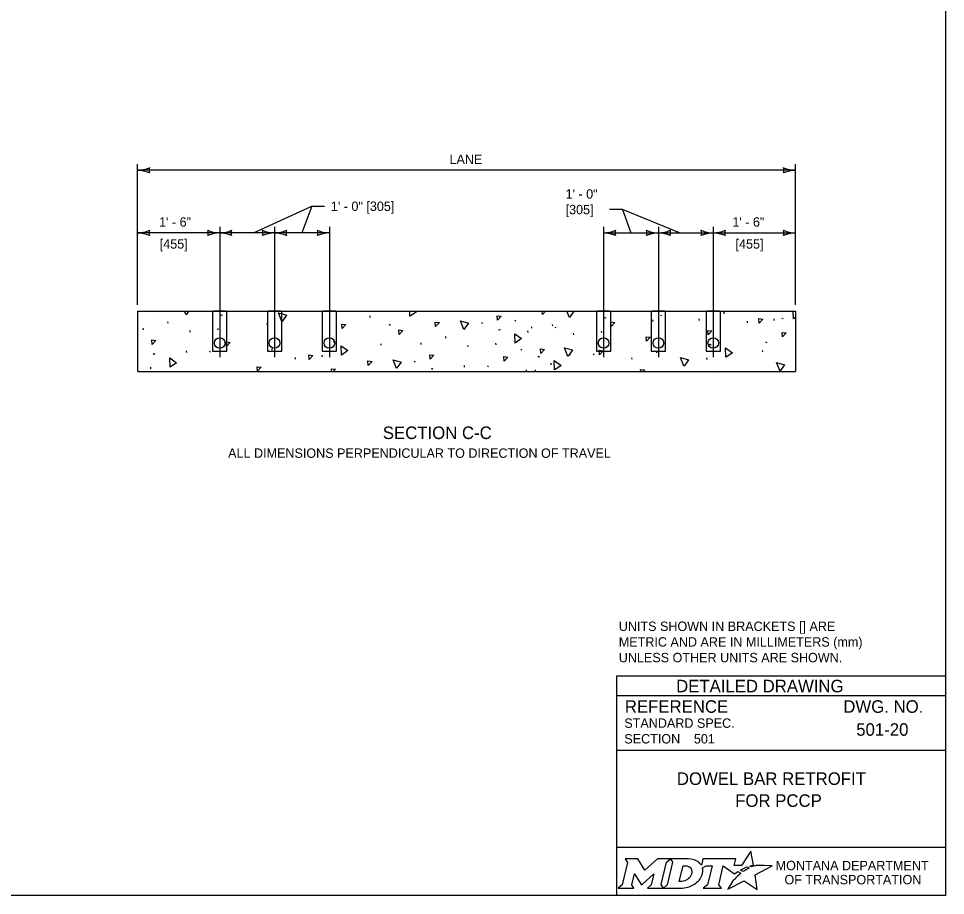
# Model space of a CAD drawing. Extents: x 49991.4 to 50021, y 49987.6 to 50011.4.
# Drawn here: x 50010.83 to 50016.75, y 49987.8 to 49993.4 of the extents above; entities that cross this region are included whole.
import ezdxf

# ---------------------------------------------------------------- set-up
doc = ezdxf.new("R2010")
doc.units = 0
for name, color, linetype in [('Default', 7, 'Continuous'), ('Level 1', 7, 'Continuous'), ('Level 2', 7, 'Continuous'), ('Level 3', 7, 'Continuous'), ('Level 4', 7, 'Continuous'), ('Level 5', 7, 'Continuous'), ('Level 9', 7, 'Continuous')]:
    doc.layers.add(name, color=color, linetype=linetype)

msp = doc.modelspace()

# ---------------------------------------------------------------- linework, layer by layer
at = {"layer": 'Default'}
for points in [[(50014.7056, 49988.0338), (50014.7197, 49988.0104), (50014.6862, 49987.8671), (50014.6605, 49987.8446), (50014.7621, 49987.8446), (50014.7486, 49987.8674), (50014.7648, 49987.9375), (50014.8085, 49987.8685), (50014.8138, 49987.8685), (50014.8889, 49987.938), (50014.8725, 49987.8669), (50014.8478, 49987.8449), (50014.9494, 49987.8449), (50014.9356, 49987.8682), (50014.9688, 49988.0106)], [(50014.9688, 49988.0106), (50014.9941, 49988.0338), (50014.9117, 49988.0338), (50014.8321, 49987.9608), (50014.7876, 49988.0335), (50014.7056, 49988.0338)], [(50015.1077, 49988.0338), (50014.9941, 49988.0338), (50015.0088, 49988.0109), (50014.9749, 49987.8671), (50014.9494, 49987.8449), (50015.06, 49987.8449)], [(50015.5126, 49987.9811), (50015.5023, 49987.9867), (50015.5139, 49987.9895), (50015.5255, 49987.9915), (50015.5081, 49988.0816), (50015.4486, 49987.9903), (50015.4013, 49987.9896), (50015.4116, 49988.0337), (50015.2024, 49988.0338), (50015.1923, 49987.9913), (50015.1865, 49987.9996)], [(50015.1317, 49987.9471), (50015.1305, 49987.939), (50015.1273, 49987.9297), (50015.1231, 49987.9215), (50015.1175, 49987.914), (50015.111, 49987.9071), (50015.1031, 49987.9008), (50015.0948, 49987.8961), (50015.0857, 49987.8922), (50015.0766, 49987.8899), (50015.0674, 49987.889), (50015.0515, 49987.889), (50015.0751, 49987.989), (50015.0911, 49987.989), (50015.0987, 49987.9884), (50015.1063, 49987.9865), (50015.1129, 49987.9835), (50015.119, 49987.9793), (50015.1238, 49987.9743), (50015.1275, 49987.9683), (50015.1302, 49987.9621), (50015.1318, 49987.9547), (50015.1318, 49987.9517), (50015.1317, 49987.9471)], [(50015.1991, 49987.9747), (50015.2237, 49987.9878), (50015.2606, 49987.9878), (50015.232, 49987.8673), (50015.2045, 49987.8446), (50015.3207, 49987.8446), (50015.3037, 49987.8675), (50015.3319, 49987.9877), (50015.4032, 49987.936), (50015.4243, 49987.9511), (50015.444, 49987.9402)], [(50015.3882, 49987.8843), (50015.3729, 49987.8599), (50015.3682, 49987.8524), (50015.3624, 49987.8438), (50015.3601, 49987.8395), (50015.4654, 49987.8926), (50015.5493, 49987.8375), (50015.5362, 49987.9302), (50015.6431, 49987.9886), (50015.5938, 49987.9894), (50015.5637, 49987.9898), (50015.5429, 49987.9901), (50015.5361, 49987.9886), (50015.5312, 49987.9874), (50015.5228, 49987.9851), (50015.5126, 49987.9811)], [(50015.4622, 49987.9535), (50015.4598, 49987.9518), (50015.4415, 49987.9614), (50015.4518, 49987.9671), (50015.4559, 49987.9693), (50015.4645, 49987.9733), (50015.4702, 49987.9759), (50015.4781, 49987.9789), (50015.4854, 49987.9816), (50015.4972, 49987.9742), (50015.4932, 49987.9721), (50015.4886, 49987.9696), (50015.4844, 49987.9674), (50015.4794, 49987.9645), (50015.4775, 49987.9634), (50015.4748, 49987.9618), (50015.4723, 49987.9604), (50015.47, 49987.9588), (50015.4674, 49987.957), (50015.4647, 49987.9552), (50015.4622, 49987.9535)], [(50015.1057, 49987.8522), (50015.1141, 49987.8548), (50015.1271, 49987.8602), (50015.1475, 49987.8712)], [(50015.4021, 49987.9004), (50015.4021, 49987.9004)]]:
    msp.add_lwpolyline(points, dxfattribs=at)
for centre, radius, start, end in [((50015.1308, 49987.9554), 0.0709, 339.53292, 15.85821), ((50015.0868, 49987.9727), 0.1183, 300.91025, 339.13831)]:
    msp.add_arc(centre, radius, start, end, dxfattribs=at)
for centre, major_axis, ratio, start_param, end_param in [((50015.1056, 49987.9864), (0.0834, -0.0037), 0.568097, 0.61298, 1.570796), ((50015.1612, 49987.9937), (0.0361, -0.0295), 0.469099, 1.225588, 1.570796), ((50015.4119, 49987.9106), (-0.0098, -0.0102), 0.016458, 3.141593, 6.279097), ((50015.4329, 49987.9305), (-0.0112, -0.0097), 0.021651, 3.157348, 6.283185), ((50015.3952, 49987.8923), (-0.00694, -0.00806), 0.008222, 0, 3.137361), ((50015.0603, 49987.9932), (0, 0.1484), 0.987302, 3.139398, 3.456847)]:
    msp.add_ellipse(centre, major_axis=major_axis, ratio=ratio, start_param=start_param, end_param=end_param, dxfattribs=at)
at = {"layer": 'Level 1'}
for p, q in [((50011.5929, 49991.5298), (50011.5929, 49991.1448)), ((50011.5929, 49991.5298), (50015.7929, 49991.5298)), ((50015.7929, 49991.5298), (50015.7929, 49991.1448)), ((50011.5952, 49991.1448), (50015.7929, 49991.1448))]:
    msp.add_line(p, q, dxfattribs=at)
msp.add_lwpolyline([(49999.3835, 49998.9992), (50016.7501, 49998.9992), (50016.7501, 49987.7988), (49999.3835, 49987.7988)], close=True, dxfattribs=at)
at = {"layer": 'Level 3'}
for p, q in [((50011.5929, 49991.5698), (50011.5929, 49992.4698)), ((50015.7929, 49992.4298), (50011.5929, 49992.4298)), ((50015.7929, 49991.5698), (50015.7929, 49992.4698)), ((50012.7055, 49992.2002), (50012.7874, 49992.2002)), ((50014.6882, 49992.179), (50014.6062, 49992.179)), ((50012.1179, 49992.0298), (50011.5929, 49992.0298)), ((50012.4679, 49992.0298), (50012.1179, 49992.0298)), ((50012.8179, 49992.0298), (50012.4679, 49992.0298)), ((50014.5679, 49992.0298), (50014.9179, 49992.0298)), ((50014.9179, 49992.0298), (50015.2679, 49992.0298)), ((50015.2679, 49992.0298), (50015.7929, 49992.0298))]:
    msp.add_line(p, q, dxfattribs=at)
for points in [[(50012.3342, 49992.0298), (50012.7055, 49992.2002), (50012.6429, 49992.0298)], [(50015.0517, 49992.0298), (50014.6882, 49992.179), (50014.7429, 49992.0298)]]:
    msp.add_lwpolyline(points, dxfattribs=at)
for centre in [(50012.1179, 49991.3267), (50012.4679, 49991.3267), (50012.8179, 49991.3267), (50014.5679, 49991.3267), (50014.9179, 49991.3267), (50015.2679, 49991.3267)]:
    msp.add_circle(centre, 0.0338, dxfattribs=at)
for centre, radius, start, end in [((50011.5838, 49992.6519), 0.2223, 272.36048, 292.54399), ((50011.5815, 49992.1971), 0.233, 67.92284, 87.17269), ((50011.7212, 49992.4298), 0.0548, 162.13882, 197.86118), ((50015.8021, 49992.6519), 0.2223, 247.45601, 267.63952), ((50015.6647, 49992.4298), 0.0548, 342.13882, 17.86118), ((50015.8044, 49992.1971), 0.233, 92.82731, 112.07716), ((50011.5838, 49992.2519), 0.2223, 272.36048, 292.54399), ((50011.5815, 49991.7971), 0.233, 67.92284, 87.17269), ((50011.7212, 49992.0298), 0.0548, 162.13882, 197.86118), ((50011.9897, 49992.0298), 0.0548, 342.13882, 17.86118), ((50012.1294, 49992.2625), 0.233, 247.92284, 267.17269), ((50012.1271, 49991.8076), 0.2223, 92.36048, 112.54399), ((50012.1088, 49992.2519), 0.2223, 272.36048, 292.54399), ((50012.1065, 49991.7971), 0.233, 67.92284, 87.17269), ((50012.2462, 49992.0298), 0.0548, 162.13882, 197.86118), ((50012.3397, 49992.0298), 0.0548, 342.13882, 17.86118), ((50012.4794, 49992.2625), 0.233, 247.92284, 267.17269), ((50012.4771, 49991.8076), 0.2223, 92.36048, 112.54399), ((50012.4588, 49992.2519), 0.2223, 272.36048, 292.54399), ((50012.4565, 49991.7971), 0.233, 67.92284, 87.17269), ((50012.5962, 49992.0298), 0.0548, 162.13882, 197.86118), ((50012.6897, 49992.0298), 0.0548, 342.13882, 17.86118), ((50012.8294, 49992.2625), 0.233, 247.92284, 267.17269), ((50012.8271, 49991.8076), 0.2223, 92.36048, 112.54399), ((50014.5564, 49992.2625), 0.233, 272.82731, 292.07716), ((50014.5588, 49991.8076), 0.2223, 67.45601, 87.63952), ((50014.6961, 49992.0298), 0.0548, 162.13882, 197.86118), ((50014.9271, 49992.2519), 0.2223, 247.45601, 267.63952), ((50014.7897, 49992.0298), 0.0548, 342.13882, 17.86118), ((50014.9294, 49991.7971), 0.233, 92.82731, 112.07716), ((50014.9064, 49992.2625), 0.233, 272.82731, 292.07716), ((50014.9088, 49991.8076), 0.2223, 67.45601, 87.63952), ((50015.0461, 49992.0298), 0.0548, 162.13882, 197.86118), ((50015.2771, 49992.2519), 0.2223, 247.45601, 267.63952), ((50015.1397, 49992.0298), 0.0548, 342.13882, 17.86118), ((50015.2794, 49991.7971), 0.233, 92.82731, 112.07716), ((50015.2564, 49992.2625), 0.233, 272.82731, 292.07716), ((50015.2588, 49991.8076), 0.2223, 67.45601, 87.63952), ((50015.3961, 49992.0298), 0.0548, 162.13882, 197.86118), ((50015.8021, 49992.2519), 0.2223, 247.45601, 267.63952), ((50015.6647, 49992.0298), 0.0548, 342.13882, 17.86118), ((50015.8044, 49991.7971), 0.233, 92.82731, 112.07716)]:
    msp.add_arc(centre, radius, start, end, dxfattribs=at)
at = {"layer": 'Level 4'}
for p, q in [((50014.4676, 49991.5298), (50014.4681, 49991.5291)), ((50012.1233, 49991.5071), (50012.1299, 49991.5038)), ((50012.128, 49991.5071), (50012.1347, 49991.5038)), ((50013.0792, 49991.4904), (50013.0782, 49991.5006)), ((50014.0007, 49991.4727), (50014.0074, 49991.4694)), ((50014.5708, 49991.4904), (50014.5775, 49991.4871)), ((50014.5756, 49991.4905), (50014.5823, 49991.4871)), ((50014.8842, 49991.4643), (50014.8831, 49991.4745)), ((50014.9307, 49991.5054), (50014.9374, 49991.5021)), ((50015.1801, 49991.4712), (50015.1791, 49991.4813)), ((50015.3377, 49991.5131), (50015.3367, 49991.5233)), ((50015.4872, 49991.4562), (50015.4861, 49991.4664)), ((50015.6578, 49991.4705), (50015.6568, 49991.4807)), ((50015.7066, 49991.4863), (50015.7133, 49991.483)), ((50011.631, 49991.4107), (50011.6299, 49991.4208)), ((50011.7886, 49991.4527), (50011.7875, 49991.4628)), ((50011.9303, 49991.3957), (50011.9293, 49991.4059)), ((50012.1087, 49991.41), (50012.1076, 49991.4202)), ((50012.4227, 49991.4405), (50012.4216, 49991.4506)), ((50013.1996, 49991.4469), (50013.2051, 49991.4393)), ((50013.7882, 49991.4595), (50013.7938, 49991.4519)), ((50013.8966, 49991.4133), (50013.9032, 49991.41)), ((50013.9013, 49991.4133), (50013.908, 49991.41)), ((50014.1111, 49991.4209), (50014.11, 49991.4311)), ((50014.2434, 49991.436), (50014.2424, 49991.4461)), ((50014.2564, 49991.4283), (50014.2631, 49991.4249)), ((50013.5619, 49991.3588), (50013.5608, 49991.369)), ((50014.0858, 49991.394), (50014.0848, 49991.4042)), ((50014.3779, 49991.3791), (50014.3769, 49991.3892)), ((50014.5563, 49991.3933), (50014.5552, 49991.4035)), ((50012.4532, 49991.2817), (50012.4521, 49991.2918)), ((50012.8429, 49991.3361), (50012.8496, 49991.3328)), ((50013.1493, 49991.3122), (50013.1482, 49991.3223)), ((50013.4043, 49991.3169), (50013.4032, 49991.327)), ((50013.7036, 49991.3019), (50013.7026, 49991.312)), ((50013.882, 49991.3162), (50013.8809, 49991.3263)), ((50014.04, 49991.2885), (50014.0456, 49991.2809)), ((50015.2426, 49991.3194), (50015.2493, 49991.3161)), ((50015.2474, 49991.3195), (50015.2541, 49991.3162)), ((50015.6024, 49991.3344), (50015.6091, 49991.3311)), ((50011.6935, 49991.259), (50011.7002, 49991.2556)), ((50011.6982, 49991.259), (50011.7049, 49991.2557)), ((50011.908, 49991.2666), (50011.9069, 49991.2768)), ((50012.0533, 49991.2739), (50012.06, 49991.2706)), ((50012.6021, 49991.2247), (50012.601, 49991.2349)), ((50012.7733, 49991.239), (50012.7722, 49991.2492)), ((50014.1483, 49991.2423), (50014.155, 49991.239)), ((50014.1531, 49991.2423), (50014.1598, 49991.239)), ((50014.3556, 49991.2499), (50014.3545, 49991.2601)), ((50014.5009, 49991.2573), (50014.5076, 49991.254)), ((50014.7503, 49991.2231), (50014.7493, 49991.2332)), ((50014.908, 49991.265), (50014.9069, 49991.2752)), ((50015.2281, 49991.2224), (50015.227, 49991.2325)), ((50015.5841, 49991.2699), (50015.5831, 49991.28)), ((50011.6789, 49991.1619), (50011.6779, 49991.172)), ((50013.3585, 49991.2113), (50013.364, 49991.2038)), ((50013.6813, 49991.1728), (50013.6802, 49991.1829)), ((50013.8266, 49991.1801), (50013.8333, 49991.1768)), ((50014.2337, 49991.1879), (50014.2326, 49991.198)), ((50013.4668, 49991.1651), (50013.4735, 49991.1618)), ((50013.4715, 49991.1652), (50013.4782, 49991.1618)), ((50014.0761, 49991.1459), (50014.075, 49991.156)), ((50014.1338, 49991.1452), (50014.1327, 49991.1554))]:
    msp.add_line(p, q, dxfattribs=at)
for points in [[(50011.7229, 49991.5254), (50011.7226, 49991.5298)], [(50011.7269, 49991.5298), (50011.7229, 49991.5254)], [(50011.9031, 49991.5064), (50011.8936, 49991.5298)], [(50011.9197, 49991.5298), (50011.9038, 49991.5072)], [(50013.3322, 49991.4978), (50013.331, 49991.5298)], [(50013.3682, 49991.5298), (50013.3732, 49991.5262), (50013.3331, 49991.4983)], [(50014.1778, 49991.5087), (50014.1762, 49991.5298)], [(50014.1971, 49991.5298), (50014.1778, 49991.5087)], [(50014.3507, 49991.4897), (50014.3344, 49991.5298)], [(50014.379, 49991.5298), (50014.3514, 49991.4905)], [(50015.7798, 49991.4811), (50015.778, 49991.5298)], [(50012.5151, 49991.4645), (50012.4926, 49991.5198), (50012.5439, 49991.5052), (50012.5158, 49991.4652)], [(50013.6764, 49991.4126), (50013.6539, 49991.468), (50013.7052, 49991.4533), (50013.6771, 49991.4134)], [(50013.8903, 49991.4718), (50013.8881, 49991.5005), (50013.9138, 49991.4974), (50013.8903, 49991.4718)], [(50015.5602, 49991.4543), (50015.5581, 49991.483), (50015.5838, 49991.4799), (50015.5602, 49991.4543)], [(50015.7929, 49991.4901), (50015.7807, 49991.4816)], [(50012.9004, 49991.419), (50012.8982, 49991.4477), (50012.9239, 49991.4446), (50012.9004, 49991.419)], [(50013.2625, 49991.3822), (50013.2603, 49991.4108), (50013.286, 49991.4077), (50013.2625, 49991.3822)], [(50013.4962, 49991.4316), (50013.494, 49991.4602), (50013.5197, 49991.4571), (50013.4962, 49991.4316)], [(50014.6169, 49991.4327), (50014.6147, 49991.4614), (50014.6404, 49991.4583), (50014.6169, 49991.4327)], [(50015.2363, 49991.378), (50015.2341, 49991.4067), (50015.2598, 49991.4036), (50015.2363, 49991.378)], [(50014.0039, 49991.3268), (50014.0017, 49991.3865), (50014.0449, 49991.3552), (50014.0048, 49991.3273)], [(50014.8423, 49991.3378), (50014.8401, 49991.3664), (50014.8658, 49991.3633), (50014.8423, 49991.3378)], [(50015.7101, 49991.3655), (50015.7079, 49991.3941), (50015.7336, 49991.391), (50015.7101, 49991.3655)], [(50011.6872, 49991.3175), (50011.685, 49991.3462), (50011.7107, 49991.3431), (50011.6872, 49991.3175)], [(50012.161, 49991.305), (50012.1588, 49991.3337), (50012.1845, 49991.3306), (50012.161, 49991.305)], [(50012.8952, 49991.2496), (50012.893, 49991.3094), (50012.9362, 49991.2781), (50012.8961, 49991.2501)], [(50014.168, 49991.2606), (50014.1658, 49991.2892), (50014.1915, 49991.2861), (50014.168, 49991.2606)], [(50014.3409, 49991.2416), (50014.3184, 49991.297), (50014.3697, 49991.2823), (50014.3416, 49991.2424)], [(50015.3489, 49991.2354), (50015.3467, 49991.2951), (50015.3899, 49991.2638), (50015.3498, 49991.2359)], [(50011.8008, 49991.1725), (50011.7986, 49991.2322), (50011.8418, 49991.2009), (50011.8017, 49991.173)], [(50012.6883, 49991.2225), (50012.6861, 49991.2512), (50012.7118, 49991.2481), (50012.6883, 49991.2225)], [(50013.4605, 49991.2237), (50013.4583, 49991.2524), (50013.484, 49991.2493), (50013.4605, 49991.2237)], [(50013.9343, 49991.2112), (50013.9321, 49991.2398), (50013.9578, 49991.2367), (50013.9343, 49991.2112)], [(50014.5411, 49991.2516), (50014.5389, 49991.2802), (50014.5646, 49991.2771), (50014.5411, 49991.2516)], [(50015.0806, 49991.1788), (50015.0581, 49991.2342), (50015.1094, 49991.2196), (50015.0813, 49991.1796)], [(50012.3589, 49991.1466), (50012.3568, 49991.1752), (50012.3825, 49991.1721), (50012.3589, 49991.1466)], [(50013.0664, 49991.1834), (50013.0642, 49991.2121), (50013.09, 49991.209), (50013.0664, 49991.1834)], [(50013.2466, 49991.1644), (50013.2241, 49991.2198), (50013.2754, 49991.2052), (50013.2473, 49991.1652)], [(50014.2557, 49991.1558), (50014.2535, 49991.2155), (50014.2967, 49991.1842), (50014.2566, 49991.1563)], [(50015.6942, 49991.1478), (50015.6717, 49991.2032), (50015.723, 49991.1885), (50015.6949, 49991.1486)], [(50012.8319, 49991.1448), (50012.8305, 49991.1627), (50012.8563, 49991.1596), (50012.8426, 49991.1448)], [(50014.8054, 49991.1448), (50014.8043, 49991.1585), (50014.8301, 49991.1554), (50014.8202, 49991.1448)], [(50015.2782, 49991.1448), (50015.2781, 49991.146), (50015.2884, 49991.1448)]]:
    msp.add_lwpolyline(points, dxfattribs=at)
at = {"layer": 'Level 5'}
for p, q in [((50012.1179, 49992.0698), (50012.1179, 49991.2367)), ((50012.4679, 49992.0698), (50012.4679, 49991.2367)), ((50012.8179, 49992.0698), (50012.8179, 49991.2367)), ((50014.5679, 49992.0698), (50014.5679, 49991.2367)), ((50014.9179, 49992.0698), (50014.9179, 49991.2367)), ((50015.2679, 49992.0698), (50015.2679, 49991.2367)), ((50016.7501, 49989.1988), (50014.6501, 49989.1988)), ((50014.6501, 49989.1988), (50014.6501, 49987.7988)), ((50016.7501, 49989.0738), (50014.6501, 49989.0738)), ((50016.7501, 49988.7238), (50014.6501, 49988.7238)), ((50016.7501, 49988.1057), (50014.6501, 49988.1057))]:
    msp.add_line(p, q, dxfattribs=at)
at = {"layer": 'Level 9'}
for p, q in [((50012.1582, 49991.5298), (50012.0777, 49991.5298)), ((50012.5082, 49991.5298), (50012.4277, 49991.5298)), ((50012.8582, 49991.5298), (50012.7777, 49991.5298)), ((50014.6082, 49991.5298), (50014.5276, 49991.5298)), ((50014.9582, 49991.5298), (50014.8776, 49991.5298)), ((50015.3082, 49991.5298), (50015.2276, 49991.5298)), ((50012.0719, 49991.5239), (50012.0719, 49991.3561)), ((50012.164, 49991.3561), (50012.164, 49991.5239)), ((50012.4219, 49991.5239), (50012.4219, 49991.3561)), ((50012.514, 49991.3561), (50012.514, 49991.5239)), ((50012.7719, 49991.5239), (50012.7719, 49991.3561)), ((50012.8641, 49991.3561), (50012.8641, 49991.5239)), ((50014.5218, 49991.5239), (50014.5218, 49991.3561)), ((50014.614, 49991.3561), (50014.614, 49991.5239)), ((50014.8718, 49991.5239), (50014.8718, 49991.3561)), ((50014.964, 49991.3561), (50014.964, 49991.5239)), ((50015.2218, 49991.5239), (50015.2218, 49991.3561)), ((50015.314, 49991.3561), (50015.314, 49991.5239)), ((50012.0719, 49991.3561), (50012.0719, 49991.2757)), ((50012.164, 49991.2757), (50012.164, 49991.3561)), ((50012.4219, 49991.3561), (50012.4219, 49991.2757)), ((50012.514, 49991.2757), (50012.514, 49991.3561)), ((50012.7719, 49991.3561), (50012.7719, 49991.2757)), ((50012.8641, 49991.2757), (50012.8641, 49991.3561)), ((50014.5218, 49991.3561), (50014.5218, 49991.2757)), ((50014.614, 49991.2757), (50014.614, 49991.3561)), ((50014.8718, 49991.3561), (50014.8718, 49991.2757)), ((50014.964, 49991.2757), (50014.964, 49991.3561)), ((50015.2218, 49991.3561), (50015.2218, 49991.2757)), ((50015.314, 49991.2757), (50015.314, 49991.3561)), ((50012.0719, 49991.2757), (50012.164, 49991.2757)), ((50012.4219, 49991.2757), (50012.514, 49991.2757)), ((50012.7719, 49991.2757), (50012.8641, 49991.2757)), ((50014.5218, 49991.2757), (50014.614, 49991.2757)), ((50014.8718, 49991.2757), (50014.964, 49991.2757)), ((50015.2218, 49991.2757), (50015.314, 49991.2757))]:
    msp.add_line(p, q, dxfattribs=at)
for centre, start, end in [((50012.0777, 49991.5239), 90, 180), ((50012.1582, 49991.5239), 0, 90), ((50012.4277, 49991.5239), 90, 180), ((50012.5082, 49991.5239), 0, 90), ((50012.7777, 49991.5239), 90, 180), ((50012.8582, 49991.5239), 0, 90), ((50014.5276, 49991.5239), 90, 180), ((50014.6082, 49991.5239), 0, 90), ((50014.8776, 49991.5239), 90, 180), ((50014.9582, 49991.5239), 0, 90), ((50015.2276, 49991.5239), 90, 180), ((50015.3082, 49991.5239), 0, 90)]:
    msp.add_arc(centre, 0.00583, start, end, dxfattribs=at)

# ---------------------------------------------------------------- texts
at = {"layer": 'Default'}
for s, p in [('MONTANA DEPARTMENT', (50015.6663, 49987.96)), ('OF TRANSPORTATION', (50015.7225, 49987.87))]:
    msp.add_text(s, height=0.06, rotation=360, dxfattribs=at).set_placement(p)
at = {"layer": 'Level 2'}
for s, height, p in [('LANE', 0.06, (50013.5845, 49992.4698)), ('1\' - 0"', 0.06, (50014.3257, 49992.249)), ('1\' - 0" [305]', 0.06, (50012.8274, 49992.1702)), ('[305]', 0.06, (50014.3257, 49992.149)), ('1\' - 6"', 0.06, (50011.7307, 49992.0698)), ('1\' - 6"', 0.06, (50015.3899, 49992.0698)), ('[455]', 0.06, (50011.7352, 49991.9298)), ('[455]', 0.06, (50015.4102, 49991.9298)), ('SECTION C-C', 0.08, (50013.159, 49990.7136)), ('ALL DIMENSIONS PERPENDICULAR TO DIRECTION OF TRAVEL', 0.06, (50012.1715, 49990.5936)), ('UNITS SHOWN IN BRACKETS [] ARE ', 0.06, (50014.6651, 49989.488)), ('METRIC AND ARE IN MILLIMETERS (mm) ', 0.06, (50014.6651, 49989.388)), ('UNLESS OTHER UNITS ARE SHOWN.', 0.06, (50014.6651, 49989.288)), ('501-20', 0.08, (50016.1805, 49988.8187)), ('501', 0.06, (50015.1444, 49988.7693)), ('DOWEL BAR RETROFIT', 0.08, (50015.0359, 49988.5047)), ('FOR PCCP', 0.08, (50015.408, 49988.3647))]:
    msp.add_text(s, height=height, dxfattribs=at).set_placement(p)
at = {"layer": 'Level 5'}
for s, height, p in [('DETAILED DRAWING', 0.0799, (50015.0311, 49989.0963)), ('REFERENCE', 0.08, (50014.7037, 49988.9654)), ('DWG. NO.', 0.08, (50016.0979, 49988.9654)), ('STANDARD SPEC.', 0.06, (50014.7004, 49988.8694)), ('SECTION', 0.06, (50014.7004, 49988.7694))]:
    msp.add_text(s, height=height, dxfattribs=at).set_placement(p)

doc.saveas('drawing.dxf')
